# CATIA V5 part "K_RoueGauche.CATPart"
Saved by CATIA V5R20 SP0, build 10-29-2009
Part number: roue_gauche
Publications: "Corps principal", "largeur pivot", "largeur de la glissière", "Longueur de barres du corps", "Point.1", "Droite.1", "Droite.2", "Droite.3", "Droite.4", "Droite.5"
Bounding box of the stored display mesh (mm): x -100 to 100, y 575 to 625, z -100 to 100
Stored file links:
  G:\Khaled_CFAO_2011\ST2M\ST2M_GR1\cdurantin\cdurantin\Khaled\CAD_ThinkMOTION\K_RoueGauche.CATPart
  G:\Khaled_CFAO_2011\ST2M\ST2M_GR1\cdurantin\cdurantin\Khaled\CAD_ThinkMOTION\K_PivotRoueGauche.CATPart
  G:\Khaled_CFAO_2011\ST2M\ST2M_GR1\cdurantin\cdurantin\Khaled\CAD_ThinkMOTION\K_Part4.CATPart
  G:\Khaled_CFAO_2011\ST2M\ST2M_GR1\cdurantin\cdurantin\Khaled\CAD_ThinkMOTION\K_Corps.CATPart
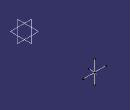
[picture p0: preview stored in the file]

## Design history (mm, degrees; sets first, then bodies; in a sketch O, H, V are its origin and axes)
External parameters (linked from other documents)
  `External.largeur pivot` = 125 mm
  `External.largeur de la glissière` = 100 mm
  `External.Longueur de barres du corps` = 800 mm
Body1 (main body)
  Point1: type OnPlane, Support xy-plane, H 0, V 625 {= `External.largeur pivot` +`External.largeur de la glissière` +`External.Longueur de barres du corps` /2}, Direction (1, 0, 0)
  Line1: type PtDir, RefPoint Point1, Direction zx-plane, Start 0, End -50
  Line2: type PtDir, RefPoint Point1, Direction yz-plane, Start 0, End 100
  Line3: type PtDir, RefPoint Point1, Direction yz-plane, Start 0, End -100
  Line4: type PtDir, RefPoint Point1, Direction xy-plane, Start 0, End -100
  Line5: type PtDir, RefPoint Point1, Direction xy-plane, Start 0, End 100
